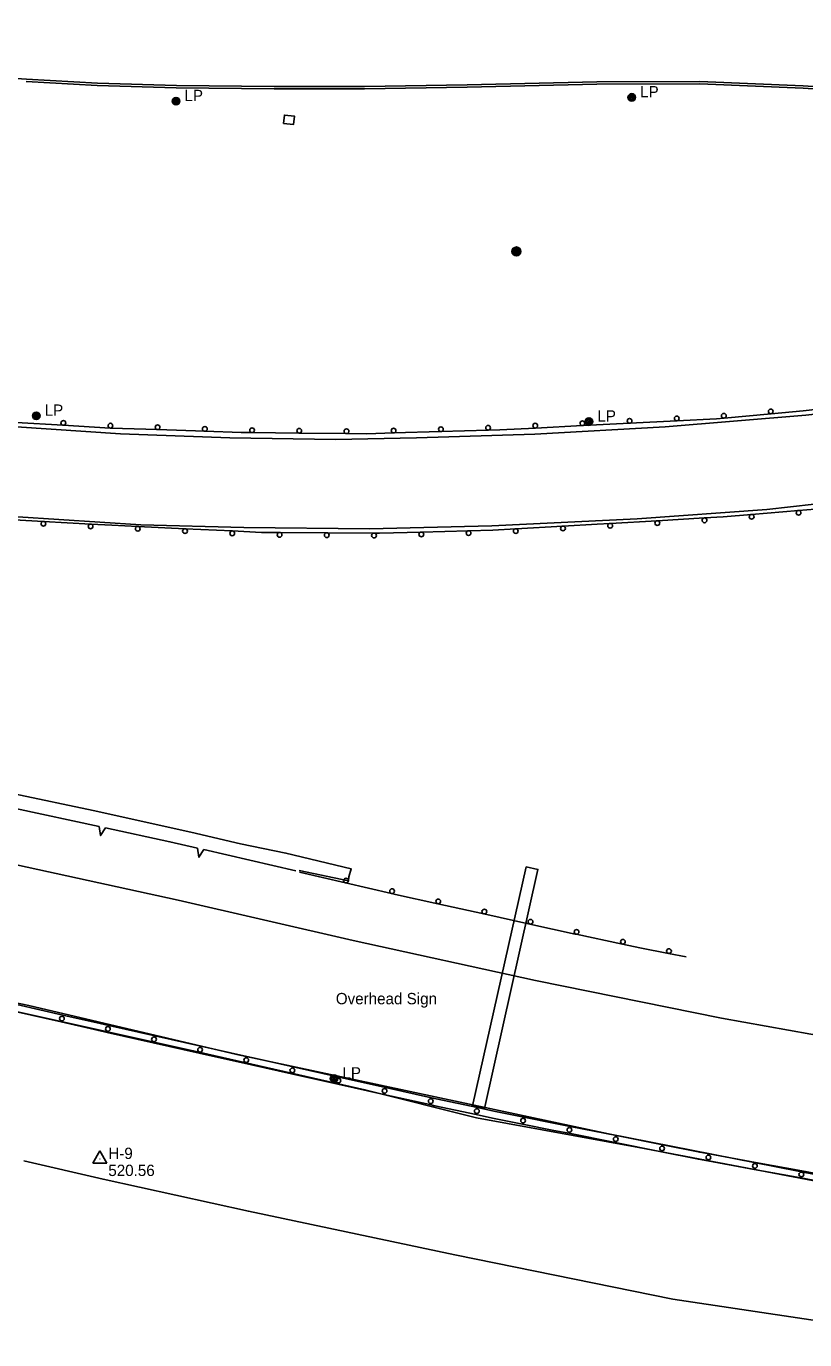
# Model space of a CAD drawing. Extents: x 2402803 to 2427059, y 6985292 to 6997652.
# Drawn here: x 2414673 to 2415003, y 6991391 to 6991947 of the extents above; entities that cross this region are included whole.
import ezdxf

# ---------------------------------------------------------------- set-up
doc = ezdxf.new("R2010")
doc.units = 0
for name, color, linetype in [('p_control ground ctrl', 7, 'Continuous'), ('p_drainage conc drain', 7, 'Continuous'), ('p_dtm retaining wall', 7, 'Continuous'), ('p_road - paved curb', 7, 'Continuous'), ('p_road bridge end', 7, 'Continuous'), ('p_road conc barrier', 7, 'Continuous'), ('p_road guard rails', 7, 'Continuous'), ('p_structure general', 7, 'Continuous'), ('p_utility manhole', 7, 'Continuous'), ('V7 LEVEL 31', 7, 'Continuous')]:
    doc.layers.add(name, color=color, linetype=linetype)

msp = doc.modelspace()

# ---------------------------------------------------------------- linework, layer by layer
at = {"layer": 'p_control ground ctrl'}
for p, q in [((2414704.45, 6991471.1), (2414701.45, 6991465.9)), ((2414707.45, 6991465.9), (2414704.45, 6991471.1)), ((2414701.45, 6991465.9), (2414707.45, 6991465.9)), ((2414704.45, 6991467.62), (2414704.45, 6991467.66))]:
    msp.add_line(p, q, dxfattribs=at)
at = {"layer": 'p_drainage conc drain'}
msp.add_lwpolyline([(2414668.12, 6991622.27), (2414701.55, 6991615.12), (2414742.9, 6991606.03), (2414764.02, 6991601.08), (2414783.16, 6991597.16), (2414810.79, 6991590.46), (2414809.72, 6991587.06), (2414809.65, 6991585.45), (2414788.81, 6991589.7)], dxfattribs=at)
at = {"layer": 'p_dtm retaining wall'}
for p, q in [((2414704.09, 6991608.38), (2414668.74, 6991615.98)), ((2414787.39, 6991589.62), (2414748.48, 6991598.61))]:
    msp.add_line(p, q, dxfattribs=at)
for points in [[(2414706.79, 6991607.8), (2414704.74, 6991604.53), (2414704.08, 6991608.39)], [(2414745.79, 6991599.23), (2414734.08, 6991601.94), (2414706.79, 6991607.8)], [(2414748.48, 6991598.61), (2414746.38, 6991595.37), (2414745.79, 6991599.23)]]:
    msp.add_lwpolyline(points, dxfattribs=at)
at = {"layer": 'p_road - paved curb'}
for points in [[(2414673.36, 6991924.78), (2414630.36, 6991927.58), (2414579.59, 6991931.72), (2414528.18, 6991937.27), (2414487.01, 6991941.49), (2414443.14, 6991947.2)], [(2415189.27, 6991898.96), (2415143.37, 6991907), (2415098.75, 6991913.02), (2415046.4, 6991918.05), (2415001.97, 6991920.96), (2414958.27, 6991922.76), (2414914.71, 6991922.68), (2414859.9, 6991921.4), (2414816.39, 6991920.71), (2414778.18, 6991920.72), (2414736.78, 6991921.13), (2414703.36, 6991922.15), (2414673.31, 6991923.78)], [(2415189.44, 6991899.94), (2415143.52, 6991907.99), (2415098.86, 6991914.01), (2415046.48, 6991919.05), (2415002.02, 6991921.96), (2414958.29, 6991923.76), (2414914.7, 6991923.68), (2414859.88, 6991922.4), (2414816.38, 6991921.71), (2414778.19, 6991921.72), (2414736.8, 6991922.13), (2414703.4, 6991923.15), (2414673.36, 6991924.78)], [(2414669.17, 6991777.54), (2414713.24, 6991774.71), (2414759.43, 6991772.92), (2414804.13, 6991772.31), (2414838.43, 6991772.98), (2414888.54, 6991774.48), (2414943.63, 6991777.56), (2415003.17, 6991782.58), (2415043.69, 6991787.03), (2415092.18, 6991793.49), (2415143.33, 6991801.88), (2415189.35, 6991811.27), (2415225.54, 6991819.23), (2415238.84, 6991822.45)], [(2414669.74, 6991739.5), (2414721.83, 6991736.05), (2414765.29, 6991735.02), (2414818.48, 6991734.36), (2414870.33, 6991735.65), (2414931.84, 6991738.62), (2414986.63, 6991742.61), (2415036.78, 6991748.23), (2415092.16, 6991755.4), (2415145.36, 6991763.34), (2415197.78, 6991774), (2415239.87, 6991783.67), (2415284.03, 6991794.69), (2415310.65, 6991801.59)], [(2414457.55, 6991639.6), (2414506.31, 6991628.74), (2414583.66, 6991611.08), (2414638.99, 6991598.78), (2414673.7, 6991591.16)], [(2414673.7, 6991591.16), (2414737.63, 6991577.16), (2414811.61, 6991560.17), (2414888.76, 6991543.22), (2414967.46, 6991527.28), (2415052.5, 6991512.02), (2415116.32, 6991501.59), (2415179.79, 6991493.09), (2415262.64, 6991482.62), (2415345.6, 6991474.21), (2415417.78, 6991468.91), (2415489.98, 6991466.07), (2415563.91, 6991463.64), (2415616.46, 6991463.14), (2415708.04, 6991465.41), (2415812.81, 6991468.13), (2415877.2, 6991470.32)], [(2414458.39, 6991577.65), (2414517.92, 6991564.45), (2414584.38, 6991549.49), (2414632.62, 6991538.28), (2414673.41, 6991529.13)], [(2414459.12, 6991581.65), (2414520.3, 6991567.01), (2414591.25, 6991550.91), (2414650.1, 6991537.74), (2414674.35, 6991532.57)], [(2414674.35, 6991532.57), (2414762.38, 6991511.89), (2414919.7, 6991478.33), (2415008.5, 6991460.75), (2415098.74, 6991445.49), (2415182.42, 6991434.06), (2415263.3, 6991424.42), (2415354.89, 6991415.17), (2415441.13, 6991409.73), (2415512.25, 6991405.41), (2415585.22, 6991402.34), (2415669.79, 6991402.23), (2415743.85, 6991402.13), (2415813.42, 6991402.87), (2415875.22, 6991403.75)], [(2414673.41, 6991529.13), (2414743.99, 6991513.46), (2414816.62, 6991496.92), (2414863.83, 6991485.02), (2414932.45, 6991472.45), (2415014.82, 6991456.77), (2415095.64, 6991443.63), (2415172.46, 6991432.7), (2415271.49, 6991420.97), (2415357.55, 6991413.02), (2415428.56, 6991407.52), (2415505.51, 6991403.36), (2415590.03, 6991400.25), (2415667.44, 6991399.76), (2415743.66, 6991399.9), (2415820.98, 6991400.77), (2415875.9, 6991401.48)], [(2414672.22, 6991466.82), (2414705.77, 6991459.05), (2414767.28, 6991445.52), (2414854.65, 6991427.07), (2414946.89, 6991408.27), (2415034.55, 6991395.21), (2415132.47, 6991380.41), (2415221.13, 6991369.34), (2415307.89, 6991359.02), (2415382.7, 6991353.57), (2415461.83, 6991349.02), (2415541.78, 6991344.8), (2415626.95, 6991341.77), (2415697.59, 6991342.2), (2415782.51, 6991341.12), (2415841.95, 6991339.2), (2415884.63, 6991336.77)]]:
    msp.add_lwpolyline(points, dxfattribs=at)
at = {"layer": 'p_road bridge end'}
msp.add_lwpolyline([(2414782.12, 6991906.02), (2414786.35, 6991905.56), (2414786.74, 6991909.16), (2414782.51, 6991909.62)], close=True, dxfattribs=at)
at = {"layer": 'p_road conc barrier'}
for p, q in [((2414669.28, 6991532.99), (2414688.72, 6991528.57)), ((2414668.61, 6991530.07), (2414688.05, 6991525.64)), ((2414707.51, 6991521.22), (2414727.02, 6991516.83)), ((2414708.17, 6991524.15), (2414727.68, 6991519.76)), ((2414727.02, 6991516.83), (2414746.53, 6991512.44)), ((2414727.68, 6991519.76), (2414747.19, 6991515.37)), ((2414746.53, 6991512.44), (2414766.04, 6991508.05)), ((2414747.19, 6991515.37), (2414766.7, 6991510.97)), ((2414786.21, 6991506.62), (2414805.73, 6991502.27)), ((2414785.56, 6991503.69), (2414805.08, 6991499.34)), ((2414805.08, 6991499.34), (2414824.6, 6991494.99)), ((2414805.73, 6991502.27), (2414825.25, 6991497.92)), ((2414824.6, 6991494.99), (2414844.11, 6991490.64)), ((2414825.25, 6991497.92), (2414844.77, 6991493.57)), ((2414902.82, 6991478.49), (2414922.43, 6991474.57)), ((2414903.41, 6991481.43), (2414923.02, 6991477.51)), ((2414923.02, 6991477.51), (2414942.63, 6991473.59)), ((2414922.43, 6991474.57), (2414942.04, 6991470.65)), ((2414961.66, 6991466.8), (2414981.33, 6991463.2)), ((2414962.2, 6991469.75), (2414981.87, 6991466.15)), ((2414981.87, 6991466.15), (2415001.54, 6991462.56)), ((2414981.33, 6991463.2), (2415001, 6991459.61))]:
    msp.add_line(p, q, dxfattribs=at)
for points in [[(2414688.72, 6991528.57), (2414704.63, 6991524.94), (2414708.17, 6991524.15)], [(2414688.05, 6991525.64), (2414703.96, 6991522.02), (2414707.51, 6991521.22)], [(2414766.7, 6991510.97), (2414769.27, 6991510.4), (2414786.21, 6991506.62)], [(2414766.04, 6991508.05), (2414768.62, 6991507.47), (2414785.56, 6991503.69)], [(2414844.77, 6991493.57), (2414846.81, 6991493.12), (2414864.27, 6991489.37)], [(2414844.11, 6991490.64), (2414846.16, 6991490.19), (2414863.64, 6991486.43)], [(2414864.27, 6991489.37), (2414871.14, 6991487.89), (2414883.81, 6991485.35)], [(2414863.64, 6991486.43), (2414870.53, 6991484.95), (2414883.22, 6991482.41)], [(2414883.22, 6991482.41), (2414896.49, 6991479.75), (2414902.82, 6991478.49)], [(2414883.81, 6991485.35), (2414897.08, 6991482.69), (2414903.41, 6991481.43)], [(2414942.63, 6991473.59), (2414958.29, 6991470.46), (2414962.2, 6991469.75)], [(2414942.04, 6991470.65), (2414957.73, 6991467.52), (2414961.66, 6991466.8)], [(2415001.54, 6991462.56), (2415017.18, 6991459.7), (2415021.19, 6991459.01)], [(2415001, 6991459.61), (2415016.66, 6991456.74), (2415020.68, 6991456.05)]]:
    msp.add_lwpolyline(points, dxfattribs=at)
for centre in [(2414688.39, 6991527.1), (2414707.84, 6991522.68), (2414727.35, 6991518.29), (2414746.86, 6991513.9), (2414766.37, 6991509.51), (2414785.89, 6991505.16), (2414805.4, 6991500.81), (2414824.92, 6991496.46), (2414844.44, 6991492.11), (2414863.95, 6991487.9), (2414883.51, 6991483.88), (2414903.12, 6991479.96), (2414922.73, 6991476.04), (2414942.33, 6991472.12), (2414961.93, 6991468.27), (2414981.6, 6991464.68), (2415001.27, 6991461.08)]:
    msp.add_circle(centre, 1, dxfattribs=at)
at = {"layer": 'p_road guard rails'}
for p, q in [((2414968.56, 6991781.3), (2414988.44, 6991783.14)), ((2414669, 6991779.44), (2414688.93, 6991778.27)), ((2414688.93, 6991778.27), (2414708.86, 6991777.1)), ((2414888.71, 6991777.11), (2414908.66, 6991778.12)), ((2414928.63, 6991779.14), (2414948.6, 6991780.16)), ((2414728.84, 6991776.42), (2414748.83, 6991775.74)), ((2414768.81, 6991775.17), (2414788.8, 6991774.96)), ((2414788.8, 6991774.96), (2414808.79, 6991774.75)), ((2414828.77, 6991775), (2414848.76, 6991775.6)), ((2414848.76, 6991775.6), (2414868.75, 6991776.2)), ((2414680.61, 6991737.59), (2414668.22, 6991738.29)), ((2414960.24, 6991739.03), (2414940.27, 6991737.87)), ((2415000.04, 6991742.2), (2414980.15, 6991740.51)), ((2414700.57, 6991736.46), (2414680.61, 6991737.59)), ((2414740.52, 6991734.47), (2414720.54, 6991735.43)), ((2414760.49, 6991733.52), (2414740.52, 6991734.47)), ((2414800.47, 6991732.74), (2414780.47, 6991732.88)), ((2414820.46, 6991732.6), (2414800.47, 6991732.74)), ((2414860.43, 6991733.62), (2414840.44, 6991733.07)), ((2414900.35, 6991735.58), (2414880.4, 6991734.45)), ((2414940.27, 6991737.87), (2414920.31, 6991736.72)), ((2414788.89, 6991589.07), (2414808.37, 6991584.56)), ((2414808.37, 6991584.56), (2414827.86, 6991580.05)), ((2414847.38, 6991575.72), (2414866.91, 6991571.41)), ((2414866.91, 6991571.41), (2414886.44, 6991567.11)), ((2414905.98, 6991562.8), (2414925.54, 6991558.64)), ((2414945.06, 6991554.66), (2414952.51, 6991553.18))]:
    msp.add_line(p, q, dxfattribs=at)
for points in [[(2414988.44, 6991783.14), (2415002.05, 6991784.4), (2415008.31, 6991785.15)], [(2414708.86, 6991777.1), (2414709.06, 6991777.09), (2414728.84, 6991776.42)], [(2414868.75, 6991776.2), (2414873.74, 6991776.35), (2414888.71, 6991777.11)], [(2414908.66, 6991778.12), (2414911.77, 6991778.28), (2414928.63, 6991779.14)], [(2414948.6, 6991780.16), (2414965.39, 6991781.01), (2414968.56, 6991781.3)], [(2414748.83, 6991775.74), (2414764.2, 6991775.22), (2414768.81, 6991775.17)], [(2414808.79, 6991774.75), (2414817.35, 6991774.66), (2414828.77, 6991775)], [(2415019.9, 6991744.43), (2415007.17, 6991742.81), (2415000.04, 6991742.2)], [(2414980.15, 6991740.51), (2414968.24, 6991739.49), (2414960.24, 6991739.03)], [(2414720.54, 6991735.43), (2414709.56, 6991735.95), (2414700.57, 6991736.46)], [(2414780.47, 6991732.88), (2414772.87, 6991732.93), (2414760.49, 6991733.52)], [(2414840.44, 6991733.07), (2414822.82, 6991732.58), (2414820.46, 6991732.6)], [(2414880.4, 6991734.45), (2414870.73, 6991733.9), (2414860.43, 6991733.62)], [(2414920.31, 6991736.72), (2414914.94, 6991736.41), (2414900.35, 6991735.58)], [(2414827.86, 6991580.05), (2414829.48, 6991579.67), (2414847.38, 6991575.72)], [(2414886.44, 6991567.11), (2414905.6, 6991562.88), (2414905.98, 6991562.8)], [(2414925.54, 6991558.64), (2414932.94, 6991557.06), (2414945.06, 6991554.66)]]:
    msp.add_lwpolyline(points, dxfattribs=at)
for centre in [(2414968.47, 6991782.3), (2414988.35, 6991784.14), (2414688.99, 6991779.27), (2414708.92, 6991778.1), (2414728.88, 6991777.42), (2414748.86, 6991776.74), (2414768.83, 6991776.17), (2414788.81, 6991775.96), (2414828.74, 6991776), (2414848.73, 6991776.6), (2414868.72, 6991777.2), (2414888.66, 6991778.11), (2414908.61, 6991779.12), (2414928.58, 6991780.14), (2414948.55, 6991781.15), (2414808.8, 6991775.75), (2414960.29, 6991738.03), (2414980.24, 6991739.51), (2415000.12, 6991741.21), (2414680.55, 6991736.59), (2414700.52, 6991735.46), (2414720.49, 6991734.43), (2414740.47, 6991733.47), (2414760.44, 6991732.52), (2414780.46, 6991731.88), (2414800.46, 6991731.74), (2414820.45, 6991731.6), (2414840.47, 6991732.07), (2414860.45, 6991732.62), (2414880.45, 6991733.45), (2414900.41, 6991734.58), (2414920.37, 6991735.72), (2414940.33, 6991736.88), (2414808.6, 6991585.53), (2414828.08, 6991581.02), (2414847.6, 6991576.7), (2414867.13, 6991572.39), (2414886.66, 6991568.08), (2414906.18, 6991563.78), (2414925.74, 6991559.61), (2414945.26, 6991555.64)]:
    msp.add_circle(centre, 1, dxfattribs=at)
at = {"layer": 'p_structure general'}
msp.add_lwpolyline([(2414884.76, 6991591.38), (2414862.12, 6991490.11), (2414867.18, 6991488.98), (2414889.82, 6991590.25)], close=True, dxfattribs=at)
at = {"layer": 'p_utility manhole'}
for centre, radius in [((2414736.69, 6991915.49), 1.6), ((2414736.69, 6991915.49), 1.3), ((2414736.69, 6991915.49), 1), ((2414736.69, 6991915.49), 0.539), ((2414929.5, 6991917.09), 1.6), ((2414929.5, 6991917.09), 1.3), ((2414929.5, 6991917.09), 1), ((2414929.5, 6991917.09), 0.539), ((2414929.5, 6991917.09), 0.192), ((2414736.69, 6991915.49), 0.192), ((2414880.71, 6991851.85), 1.9), ((2414880.71, 6991851.85), 1.44), ((2414880.71, 6991851.85), 0.973), ((2414880.71, 6991851.85), 0.539), ((2414880.71, 6991851.85), 0.192), ((2414677.51, 6991782.27), 1.6), ((2414677.51, 6991782.27), 1.3), ((2414677.51, 6991782.27), 1), ((2414677.51, 6991782.27), 0.539), ((2414677.51, 6991782.27), 0.192), ((2414911.4, 6991779.82), 1.6), ((2414911.4, 6991779.82), 1.3), ((2414911.4, 6991779.82), 1), ((2414911.4, 6991779.82), 0.539), ((2414911.4, 6991779.82), 0.192), ((2414803.52, 6991501.68), 1.6), ((2414803.52, 6991501.68), 1.3), ((2414803.52, 6991501.68), 1), ((2414803.52, 6991501.68), 0.539), ((2414803.52, 6991501.68), 0.192)]:
    msp.add_circle(centre, radius, dxfattribs=at)

# ---------------------------------------------------------------- texts
at = {"layer": 'p_control ground ctrl'}
msp.add_text('  H-9', height=4.8, dxfattribs=at).set_placement((2414704.45, 6991467.62))
at = {"layer": 'p_structure general'}
msp.add_text('Overhead Sign', height=4.8, dxfattribs=at).set_placement((2414804.28, 6991533.13))
at = {"layer": 'p_utility manhole'}
for p in [(2414929.5, 6991917.09), (2414736.69, 6991915.49), (2414677.51, 6991782.27), (2414911.4, 6991779.82), (2414803.52, 6991501.68)]:
    msp.add_text('  LP', height=4.8, dxfattribs=at).set_placement(p)
at = {"layer": 'V7 LEVEL 31'}
msp.add_text('  520.56', height=4.8, dxfattribs=at).set_placement((2414704.45, 6991460.42))

doc.saveas('drawing.dxf')
